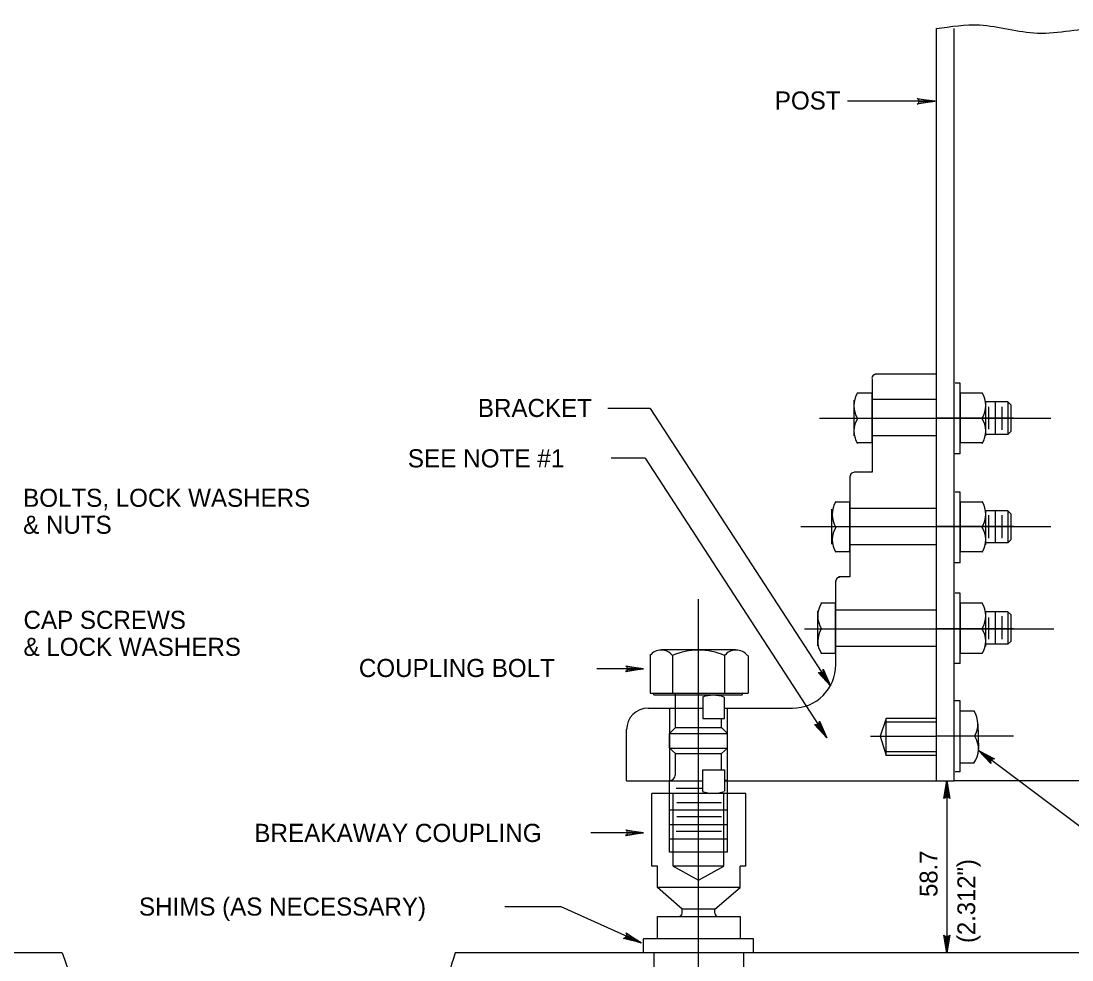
# Model space of a CAD drawing. Extents: x 637580 to 641008, y 294594 to 295782.
# Drawn here: x 637787.5 to 637964.6, y 294775.2 to 294933.4 of the extents above; entities that cross this region are included whole.
import ezdxf

# ---------------------------------------------------------------- set-up
doc = ezdxf.new("R2010")
doc.units = 0
for name, color, linetype in [('1', 7, 'Continuous'), ('2', 7, 'Continuous'), ('3', 7, 'Continuous')]:
    doc.layers.add(name, color=color, linetype=linetype)

# ---------------------------------------------------------------- blocks, each defined once
blk = doc.blocks.new('RARROW')
at = {"layer": '3'}
blk.add_lwpolyline([(-2.2695, 0.285), (-2.184875, 0.12075), (0, 0), (-2.2695, 0.285), (-2.38575, 0.384625), (0, 0), (-2.183125, -0.108), (-2.262875, -0.2705), (0, 0), (-2.38575, -0.379125), (-2.262875, -0.2705)], dxfattribs=at)

msp = doc.modelspace()

# ---------------------------------------------------------------- linework, layer by layer
at = {"layer": '2'}
for p, q in [((637941.8, 294866.5), (637941.8, 294932.13)), ((637944.8, 294805.38), (637944.8, 294932.13)), ((637941.55, 294919.88), (637926.8, 294919.88)), ((637941.8, 294873.88), (637931.43, 294873.88)), ((637930.93, 294873.13), (637930.93, 294857.38)), ((637945.8, 294872.38), (637944.93, 294872.38)), ((637945.8, 294860.5), (637945.8, 294872.38)), ((637928.43, 294870.75), (637930.93, 294870.75)), ((637930.93, 294862.38), (637930.93, 294870.75)), ((637930.93, 294862.38), (637930.93, 294870.75)), ((637945.8, 294870.75), (637945.8, 294862.38)), ((637945.8, 294870.75), (637949.55, 294870.75)), ((637927.93, 294866.5), (637927.93, 294869.5)), ((637941.8, 294869.63), (637930.93, 294869.63)), ((637950.05, 294869.25), (637950.05, 294866.5)), ((637953.8, 294869.25), (637950.05, 294869.25)), ((637950.55, 294868.38), (637950.55, 294864.63)), ((637951.68, 294869.25), (637951.68, 294863.75)), ((637952.8, 294868.38), (637952.8, 294864.5)), ((637953.8, 294869.25), (637953.8, 294863.75)), ((637953.8, 294869.25), (637954.3, 294868.75)), ((637954.3, 294868.75), (637954.3, 294864.25)), ((637893.55, 294868.13), (637886.39, 294868.13)), ((637893.55, 294868.13), (637923.93, 294821.38)), ((637922.05, 294866.5), (637961.05, 294866.5)), ((637927.93, 294866.5), (637930.93, 294866.5)), ((637927.93, 294866.5), (637927.93, 294866.5)), ((637927.93, 294863.5), (637927.93, 294866.5)), ((637930.93, 294866.5), (637930.93, 294866.5)), ((637930.93, 294866.5), (637930.93, 294866.5)), ((637930.93, 294866.5), (637930.93, 294866.5)), ((637930.93, 294866.5), (637930.93, 294866.5)), ((637930.93, 294866.5), (637930.93, 294866.5)), ((637941.8, 294848.25), (637941.8, 294866.5)), ((637954.8, 294866.5), (637941.8, 294866.5)), ((637945.8, 294866.5), (637945.8, 294866.5)), ((637945.8, 294866.5), (637950.05, 294866.5)), ((637945.8, 294866.5), (637945.8, 294866.5)), ((637950.05, 294866.5), (637950.05, 294866.5)), ((637950.05, 294866.5), (637950.05, 294863.5)), ((637950.05, 294866.5), (637950.05, 294866.5)), ((637941.8, 294863.5), (637930.93, 294863.5)), ((637953.8, 294863.75), (637950.05, 294863.75)), ((637953.8, 294863.75), (637954.3, 294864.25)), ((637928.43, 294862.38), (637930.93, 294862.38)), ((637945.8, 294862.38), (637949.43, 294862.38)), ((637892.68, 294859.75), (637886.95, 294859.75)), ((637892.68, 294859.75), (637923.3, 294812.63)), ((637945.8, 294860.5), (637944.68, 294860.5)), ((637927.18, 294856.75), (637927.18, 294839.75)), ((637930.93, 294857.38), (637927.93, 294857.38)), ((637924.8, 294852.38), (637927.18, 294852.38)), ((637927.18, 294844), (637927.18, 294852.38)), ((637927.18, 294844), (637927.18, 294852.38)), ((637927.18, 294844), (637927.18, 294852.38)), ((637945.8, 294854), (637944.93, 294854)), ((637945.8, 294842.13), (637945.8, 294854)), ((637945.8, 294852.38), (637945.8, 294844)), ((637945.8, 294852.38), (637949.55, 294852.38)), ((637924.18, 294848.25), (637924.18, 294851.13)), ((637941.8, 294851.25), (637927.18, 294851.25)), ((637950.05, 294851), (637950.05, 294848.25)), ((637953.8, 294850.88), (637950.05, 294850.88)), ((637951.68, 294850.88), (637951.68, 294845.5)), ((637953.8, 294850.88), (637953.8, 294845.5)), ((637953.8, 294850.88), (637954.3, 294850.38)), ((637950.55, 294850.13), (637950.55, 294846.25)), ((637952.8, 294850.13), (637952.8, 294846.25)), ((637954.3, 294850.38), (637954.3, 294846)), ((637918.93, 294848.25), (637961.05, 294848.25)), ((637924.18, 294848.25), (637927.18, 294848.25)), ((637924.18, 294848.25), (637924.18, 294848.25)), ((637924.18, 294845.25), (637924.18, 294848.13)), ((637927.18, 294848.25), (637927.18, 294848.25)), ((637927.18, 294848.25), (637927.18, 294848.25)), ((637927.18, 294848.25), (637927.18, 294848.25)), ((637927.18, 294848.25), (637927.18, 294848.25)), ((637927.18, 294848.25), (637927.18, 294848.25)), ((637927.18, 294848.25), (637927.18, 294848.25)), ((637927.18, 294848.25), (637927.18, 294848.25)), ((637927.18, 294848.25), (637927.18, 294848.25)), ((637941.8, 294831), (637941.8, 294848.25)), ((637954.8, 294848.25), (637941.8, 294848.25)), ((637945.8, 294848.25), (637945.8, 294848.25)), ((637945.8, 294848.25), (637945.8, 294848.25)), ((637945.8, 294848.25), (637950.05, 294848.25)), ((637945.8, 294848.25), (637945.8, 294848.25)), ((637950.05, 294848.25), (637950.05, 294848.25)), ((637950.05, 294848.25), (637950.05, 294845.13)), ((637950.05, 294848.25), (637950.05, 294848.25)), ((637953.8, 294845.5), (637950.05, 294845.5)), ((637953.8, 294845.5), (637954.3, 294846)), ((637924.8, 294844), (637927.18, 294844)), ((637941.8, 294845.13), (637927.18, 294845.13)), ((637945.8, 294844), (637949.43, 294844)), ((637945.8, 294842.13), (637944.8, 294842.13)), ((637924.8, 294839.13), (637924.8, 294825)), ((637927.18, 294839.75), (637925.3, 294839.75)), ((637945.8, 294837), (637944.93, 294837)), ((637945.8, 294825.13), (637945.8, 294837)), ((637901.68, 294768.25), (637901.68, 294836)), ((637922.3, 294835.38), (637924.8, 294835.38)), ((637924.8, 294826.88), (637924.8, 294835.38)), ((637924.8, 294826.88), (637924.8, 294835.38)), ((637924.8, 294826.88), (637924.8, 294835.38)), ((637924.8, 294826.88), (637924.8, 294835.38)), ((637945.8, 294835.38), (637945.8, 294826.88)), ((637945.8, 294835.38), (637949.55, 294835.38)), ((637921.8, 294831.13), (637921.8, 294834)), ((637941.8, 294834.13), (637924.8, 294834.13)), ((637950.05, 294833.88), (637950.05, 294831.13)), ((637953.8, 294833.88), (637950.05, 294833.88)), ((637950.55, 294832.88), (637950.55, 294829.25)), ((637951.68, 294833.88), (637951.68, 294828.38)), ((637952.8, 294833.13), (637952.8, 294829.25)), ((637953.8, 294833.88), (637953.8, 294828.38)), ((637953.8, 294833.88), (637954.3, 294833.38)), ((637954.3, 294833.38), (637954.3, 294828.88)), ((637950.05, 294831.13), (637950.05, 294828)), ((637919.55, 294831), (637961.55, 294831)), ((637921.8, 294831), (637924.8, 294831)), ((637921.8, 294831), (637921.8, 294831)), ((637921.8, 294828.13), (637921.8, 294831)), ((637924.8, 294831), (637924.8, 294831)), ((637924.8, 294831), (637924.8, 294831)), ((637924.8, 294831), (637924.8, 294831)), ((637924.8, 294831), (637924.8, 294831)), ((637924.8, 294831), (637924.8, 294831)), ((637924.8, 294831), (637924.8, 294831)), ((637924.8, 294831), (637924.8, 294831)), ((637924.8, 294831), (637924.8, 294831)), ((637924.8, 294831), (637924.8, 294831)), ((637924.8, 294831), (637924.8, 294831)), ((637941.8, 294812.88), (637941.8, 294831)), ((637954.8, 294831), (637941.8, 294831)), ((637945.8, 294831), (637945.8, 294831)), ((637945.8, 294831), (637945.8, 294831)), ((637945.8, 294831), (637945.8, 294831)), ((637945.8, 294831), (637950.05, 294831)), ((637945.8, 294831), (637945.8, 294831)), ((637950.05, 294831), (637950.05, 294831)), ((637950.05, 294831), (637950.05, 294831)), ((637941.8, 294828), (637924.8, 294828)), ((637953.8, 294828.38), (637950.05, 294828.38)), ((637953.8, 294828.38), (637954.3, 294828.88)), ((637893.55, 294826.5), (637893.55, 294826.5)), ((637893.55, 294826.5), (637893.55, 294820.13)), ((637895.43, 294827.5), (637895.43, 294827.5)), ((637895.43, 294827.5), (637897.3, 294827.5)), ((637897.3, 294827.5), (637906.05, 294827.5)), ((637897.3, 294826.5), (637897.3, 294820.13)), ((637897.3, 294826.5), (637897.3, 294826.5)), ((637901.68, 294827.5), (637901.68, 294827.5)), ((637901.68, 294793.88), (637901.68, 294827.38)), ((637906.05, 294827.5), (637907.93, 294827.5)), ((637906.05, 294826.5), (637906.05, 294820.25)), ((637906.05, 294826.5), (637906.05, 294826.5)), ((637907.93, 294827.5), (637907.93, 294827.5)), ((637910.05, 294826.5), (637910.05, 294826.5)), ((637910.05, 294826.5), (637910.05, 294820.13)), ((637922.3, 294826.88), (637924.8, 294826.88)), ((637945.8, 294826.88), (637949.43, 294826.88)), ((637892.42, 294824.25), (637884.57, 294824.25)), ((637945.8, 294825.13), (637944.8, 294825.13)), ((637893.55, 294820.13), (637910.05, 294820.13)), ((637894.18, 294819.88), (637894.05, 294820.13)), ((637894.18, 294819.88), (637909.05, 294819.88)), ((637897.8, 294814.38), (637897.8, 294820.13)), ((637901.68, 294819.88), (637901.68, 294819.88)), ((637901.68, 294819.88), (637901.68, 294819.88)), ((637902.43, 294819.5), (637902.43, 294815.88)), ((637904.18, 294819.88), (637904.18, 294819.88)), ((637906.05, 294815.88), (637906.05, 294819.5)), ((637909.05, 294819.88), (637909.18, 294820.25)), ((637945.8, 294818.88), (637944.8, 294818.88)), ((637945.8, 294806.88), (637945.8, 294818.88)), ((637893.18, 294817.63), (637902.3, 294817.63)), ((637896.8, 294817.63), (637896.8, 294805.38)), ((637906.05, 294817.63), (637917.55, 294817.63)), ((637906.55, 294805.38), (637906.55, 294817.63)), ((637945.8, 294808.38), (637945.8, 294817.13)), ((637945.8, 294808.38), (637945.8, 294817.13)), ((637948.18, 294817.13), (637945.8, 294817.13)), ((637902.43, 294815.88), (637906.05, 294815.88)), ((637904.18, 294815.88), (637904.18, 294815.88)), ((637905.55, 294814.38), (637905.55, 294815.88)), ((637933.3, 294815.88), (637932.3, 294812.88)), ((637941.8, 294815.88), (637933.3, 294815.88)), ((637933.3, 294809.63), (637933.3, 294815.88)), ((637941.8, 294815.25), (637933.3, 294815.25)), ((637889.55, 294805.38), (637889.55, 294814)), ((637896.8, 294813.38), (637897.8, 294814.38)), ((637896.8, 294813.38), (637906.55, 294813.38)), ((637896.8, 294810.88), (637896.8, 294813.38)), ((637897.8, 294814.38), (637905.55, 294814.38)), ((637906.55, 294813.38), (637905.55, 294814.38)), ((637906.55, 294810.88), (637906.55, 294813.38)), ((637948.78, 294814.93), (637948.88, 294810.69)), ((637930.68, 294812.88), (637941.8, 294812.88)), ((637932.3, 294812.88), (637933.3, 294809.63)), ((637941.8, 294805.38), (637941.8, 294812.88)), ((637954.8, 294812.88), (637941.8, 294812.88)), ((637945.8, 294812.88), (637945.8, 294812.88)), ((637945.8, 294812.88), (637945.8, 294812.88)), ((637945.8, 294812.88), (637945.8, 294812.88)), ((637945.8, 294812.88), (637945.8, 294812.88)), ((637945.8, 294812.88), (637945.8, 294812.88)), ((637948.93, 294812.88), (637945.8, 294812.88)), ((637945.8, 294812.88), (637945.8, 294812.88)), ((637896.8, 294810.88), (637906.55, 294810.88)), ((637897.8, 294810), (637896.8, 294810.88)), ((637897.8, 294806.38), (637897.8, 294810)), ((637897.8, 294810), (637905.55, 294810)), ((637901.68, 294810.63), (637901.68, 294810.63)), ((637901.68, 294810.63), (637901.68, 294810.63)), ((637905.55, 294810), (637906.55, 294810.88)), ((637905.55, 294807.25), (637905.55, 294810)), ((637941.8, 294810.25), (637933.3, 294810.25)), ((637969.48, 294795.04), (637948.86, 294810.49)), ((637941.8, 294809.63), (637933.3, 294809.63)), ((637948.09, 294808.38), (637945.8, 294808.38)), ((637902.43, 294807.25), (637906.05, 294807.25)), ((637902.43, 294803.63), (637902.43, 294807.25)), ((637904.18, 294807.25), (637904.18, 294807.25)), ((637906.05, 294807.25), (637906.05, 294803.63)), ((637945.8, 294806.88), (637944.93, 294806.88)), ((637889.55, 294805.38), (637889.55, 294805.38)), ((637889.55, 294805.38), (637902.43, 294805.38)), ((637896.8, 294795.63), (637896.8, 294805.38)), ((637901.68, 294805.38), (637901.68, 294805.38)), ((637901.68, 294805.38), (637901.68, 294805.38)), ((637906.05, 294805.38), (637944.8, 294805.38)), ((637906.55, 294795.63), (637906.55, 294805.38)), ((637943.55, 294805.38), (637943.55, 294776.38)), ((638075.05, 294805.38), (637944.8, 294805.38)), ((637893.8, 294791), (637893.8, 294803.25)), ((637909.68, 294803.25), (637893.8, 294803.25)), ((637896.8, 294793.38), (637896.8, 294803.25)), ((637897.43, 294791), (637897.43, 294803.25)), ((637897.93, 294804.13), (637902.3, 294804.13)), ((637901.68, 294803.25), (637901.68, 294803.25)), ((637901.68, 294803.25), (637901.68, 294803.25)), ((637904.18, 294803.25), (637904.18, 294803.25)), ((637905.93, 294791), (637905.93, 294803.25)), ((637906.55, 294793.38), (637906.55, 294803.25)), ((637909.68, 294791), (637909.68, 294803.25)), ((637898.05, 294801.75), (637905.55, 294801.75)), ((637896.8, 294800.5), (637906.55, 294800.5)), ((637898.05, 294799.38), (637905.55, 294799.38)), ((637896.8, 294798), (637906.55, 294798)), ((637892.42, 294796.63), (637883.56, 294796.63)), ((637897.93, 294796.88), (637905.55, 294796.88)), ((637896.8, 294795.63), (637906.55, 294795.63)), ((637901.68, 294795.63), (637901.68, 294795.63)), ((637906.55, 294793.38), (637896.8, 294793.38)), ((637894.8, 294791), (637893.8, 294791)), ((637894.8, 294787.38), (637894.8, 294791)), ((637905.93, 294791), (637897.43, 294791)), ((637897.43, 294791), (637901.68, 294788.63)), ((637901.68, 294788.63), (637905.93, 294791)), ((637908.68, 294787.38), (637908.68, 294791)), ((637909.68, 294791), (637908.68, 294791)), ((637901.68, 294788.63), (637901.68, 294788.63)), ((637898.93, 294783.75), (637894.8, 294787.38)), ((637908.68, 294787.38), (637894.8, 294787.38)), ((637904.43, 294783.75), (637908.68, 294787.38)), ((637878.55, 294784.13), (637869.06, 294784.13)), ((637892, 294778.06), (637878.55, 294784.13)), ((637904.43, 294783.75), (637898.93, 294783.75)), ((637898.93, 294783.1), (637898.93, 294783.75)), ((637904.43, 294783.1), (637904.43, 294783.75)), ((637894.8, 294782.5), (637908.68, 294782.5)), ((637894.8, 294778.75), (637894.8, 294782.5)), ((637908.68, 294782.5), (637908.68, 294778.75)), ((637910.93, 294778.75), (637892.43, 294778.75)), ((637892.43, 294776.38), (637892.43, 294778.75)), ((637901.68, 294778.75), (637901.68, 294778.75)), ((637910.93, 294776.38), (637910.93, 294778.75)), ((637794.44, 294776.38), (637673.31, 294776.38)), ((638166.68, 294776.38), (637860.68, 294776.38)), ((637910.93, 294776.38), (637892.43, 294776.38)), ((637894.18, 294776.38), (637894.18, 294773.88)), ((637909.3, 294773.88), (637909.3, 294776.38))]:
    msp.add_line(p, q, dxfattribs=at)
for centre, start, end in [((637898.33, 294783.1), 270, 0), ((637905.03, 294783.1), 180, 270)]:
    msp.add_arc(centre, 0.6, start, end, dxfattribs=at)
for centre, major_axis, start_param, end_param in [((637931.52, 294873.21), (0, -0.61), 3.141593, 4.712389), ((637932.04, 294868.59), (0, -4.18), 4.16723, 5.257548), ((637946.02, 294868.62), (0, 4.08), 4.160577, 5.264201), ((637931.77, 294864.33), (0, -3.91), 4.129616, 5.27673), ((637946.14, 294864.34), (0, 3.96), 4.15179, 5.282205), ((637927.86, 294856.74), (0, -0.61), 3.141593, 4.712389), ((637928.38, 294850.26), (0, -4.18), 4.16723, 5.257548), ((637946.02, 294850.29), (0, 4.08), 4.160577, 5.264201), ((637928.11, 294846), (0, -3.91), 4.129616, 5.27673), ((637946.14, 294846.02), (0, 3.96), 4.15179, 5.282205), ((637925.43, 294839.04), (0, -0.61), 3.141593, 4.712389), ((637925.95, 294833.17), (0, -4.18), 4.16723, 5.257548), ((637946.02, 294833.2), (0, 4.08), 4.160577, 5.264201), ((637925.68, 294828.91), (0, -3.91), 4.129616, 5.27673), ((637946.14, 294828.92), (0, 3.96), 4.15179, 5.282205), ((637901.69, 294816.68), (0, -10.74), 2.718335, 3.56485), ((637895.4, 294825.03), (0, -2.39), 2.218404, 4.064781), ((637908.01, 294824.98), (0, -2.44), 2.228521, 4.054665), ((637917.52, 294824.96), (0, -7.33), 0, 1.570796), ((637904.16, 294814.07), (0, -5.72), 2.814747, 3.468439), ((637893.22, 294813.97), (0, -3.67), 3.141593, 4.712389), ((637944.61, 294814.96), (0, 4.18), 4.19139, 5.257548), ((637944.98, 294810.73), (0, 3.91), 4.066903, 5.295162), ((637896.85, 294806.35), (0, 0.914), 3.141593, 4.712389), ((637906.58, 294806.35), (0, -0.914), 5.587635, 6.283185), ((637904.16, 294809), (0, -5.72), 5.956339, 6.610031)]:
    msp.add_ellipse(centre, major_axis=major_axis, ratio=0.996388, start_param=start_param, end_param=end_param, dxfattribs=at)
for points in [[(637941.8, 294932.13), (637949.05, 294932.75), (637958.8, 294931.38), (637969.68, 294932.25), (637980.43, 294931.38), (637990.18, 294932.25), (637999.3, 294929.75), (638009.05, 294931.75), (638018.3, 294930.25), (638028.55, 294932.75), (638039.8, 294931.75)], [(637794.44, 294776.38), (637796.31, 294766.5), (637793.69, 294758.5), (637794.44, 294746.88), (637792.69, 294737), (637795.31, 294727.63), (637793.19, 294719.13), (637795.81, 294709.38), (637793.69, 294703.13), (637794.06, 294697.25)], [(637860.68, 294776.38), (637859.3, 294768.88), (637861.55, 294760.38), (637858.93, 294748.38), (637862.05, 294737.13), (637858.93, 294727.63), (637862.05, 294718.75), (637858.43, 294709), (637860.68, 294702.13), (637860.68, 294698.13)]]:
    msp.add_spline(points, degree=3, dxfattribs=at)

# ---------------------------------------------------------------- block references
at = {"layer": '2', "xscale": 1.2574347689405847, "yscale": 1.3092961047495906}
for p in [(637941.55, 294919.88), (637892.42, 294824.25), (637892.42, 294796.63)]:
    msp.add_blockref('RARROW', p, dxfattribs=at)
at = {"layer": '2'}
for p, xscale, yscale, rotation in [((637923.92, 294821.38), 1.2574347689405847, 1.3092961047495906, -57.059664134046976), ((637923.3, 294812.63), 1.2574347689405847, 1.3092961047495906, -56.36233542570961), ((637948.86, 294810.49), 1.2574347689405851, 1.3092961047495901, 143.29217381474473), ((637943.55, 294805.38), 1.2574347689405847, 1.3092961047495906, 89.99999999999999), ((637892, 294778.06), 1.2574347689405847, 1.3092961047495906, -24.173035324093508), ((637943.55, 294776.38), 1.2574347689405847, 1.3092961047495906, -90.00000000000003)]:
    msp.add_blockref('RARROW', p, dxfattribs=dict(at, xscale=xscale, yscale=yscale, rotation=rotation))

# ---------------------------------------------------------------- texts
at = {"layer": '1'}
for s, height, p in [('CAP SCREWS', 3.044, (637787.92, 294830.98)), ('& LOCK WASHERS', 3.0442, (637787.92, 294826.43))]:
    msp.add_text(s, height=height, dxfattribs=at).set_placement(p)
for s, p in [('58.7 ', (637941.96, 294785.82)), ('(2.312")', (637948.32, 294778.05))]:
    msp.add_text(s, height=3, rotation=90, dxfattribs=at).set_placement(p)
at = {"layer": '3'}
for s, height, p in [('POST', 3.043, (637914.55, 294918.5)), ('BRACKET', 3.043, (637864.5, 294866.69)), ('SEE NOTE #1', 3.0608, (637852.69, 294858.19)), ('BOLTS, LOCK WASHERS', 3.0427, (637787.86, 294851.55)), ('& NUTS', 3.043, (637787.86, 294847.01)), ('COUPLING BOLT', 3.0442, (637844.44, 294822.87)), ('BREAKAWAY COUPLING', 3.0608, (637826.81, 294795.07)), ('SHIMS (AS NECESSARY)', 3.0427, (637807.38, 294782.67))]:
    msp.add_text(s, height=height, dxfattribs=at).set_placement(p)

doc.saveas('drawing.dxf')
